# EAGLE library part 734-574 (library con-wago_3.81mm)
Serie 734, Federleiste mit abgewinkelten Einlötstiften / Series 734, Female connector with angled solder pins Polzahl / Pole No.: 14 Bemessungsspannung / Rated Voltage: 160 V Nennstrom / Nominal Current: 10 A Lötstiftlänge: / Solder Pin Length: 3.8 mm Farbe / Color: orange / orange Stand: 01.01.2012. Die jeweils aktuellen Daten zu diesem Artikel finden Sie in unserem Produktkatalog, den Sie unter www.wago.com einsehen können. As of: 01/01/2012. Please find the newest data for this article in our product catalogue, which can be viewed under www.wago.com.
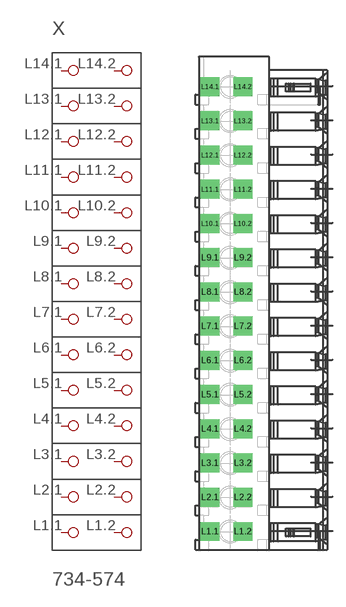
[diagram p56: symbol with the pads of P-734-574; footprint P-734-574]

Designator prefix X

## 734-574  [P-734-574]
L1.1  P1.1
L1.2  P1.2
L2.1  P2.1
L2.2  P2.2
L3.1  P3.1
L3.2  P3.2
L4.1  P4.1
L4.2  P4.2
L5.1  P5.1
L5.2  P5.2
L6.1  P6.1
L6.2  P6.2
L7.1  P7.1
L7.2  P7.2
L8.1  P8.1
L8.2  P8.2
L9.1  P9.1
L9.2  P9.2
L10.1  P10.1
L10.2  P10.2
L11.1  P11.1
L11.2  P11.2
L12.1  P12.1
L12.2  P12.2
L13.1  P13.1
L13.2  P13.2
L14.1  P14.1
L14.2  P14.2

## Footprint P-734-574 (pad centres in mm)
drill 1.4 square: L1.1 -6.016,-25.41; L1.2 -2.366,-25.41; L2.1 -6.016,-21.6; L2.2 -2.366,-21.6; L3.1 -6.016,-17.79; L3.2 -2.366,-17.79; L4.1 -6.016,-13.98; L4.2 -2.366,-13.98; L5.1 -6.016,-10.17; L5.2 -2.366,-10.17; L6.1 -6.016,-6.36; L6.2 -2.366,-6.36; L7.1 -6.016,-2.55; L7.2 -2.366,-2.55; L8.1 -6.016,1.26; L8.2 -2.366,1.26; L9.1 -6.016,5.07; L9.2 -2.366,5.07; L10.1 -6.016,8.88; L10.2 -2.366,8.88; L11.1 -6.016,12.69; L11.2 -2.366,12.69; L12.1 -6.016,16.5; L12.2 -2.366,16.5; L13.1 -6.016,20.31; L13.2 -2.366,20.31; L14.1 -6.016,24.12; L14.2 -2.366,24.12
